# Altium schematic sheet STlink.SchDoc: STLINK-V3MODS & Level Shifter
size A4; Date: Not used; ApprovedBy: Not used; CheckedBy: Not used; Author: Not used; CompanyName: STMicroelectronics; DrawnBy: Not used; Engineer: Not used; Organization: Not used; Address1: Not used; Address2: Not used; Address3: Not used; Address4: Not used; DocumentNumber: Not used; Revision: Not used; SheetNumber: 6; SheetTotal: 6
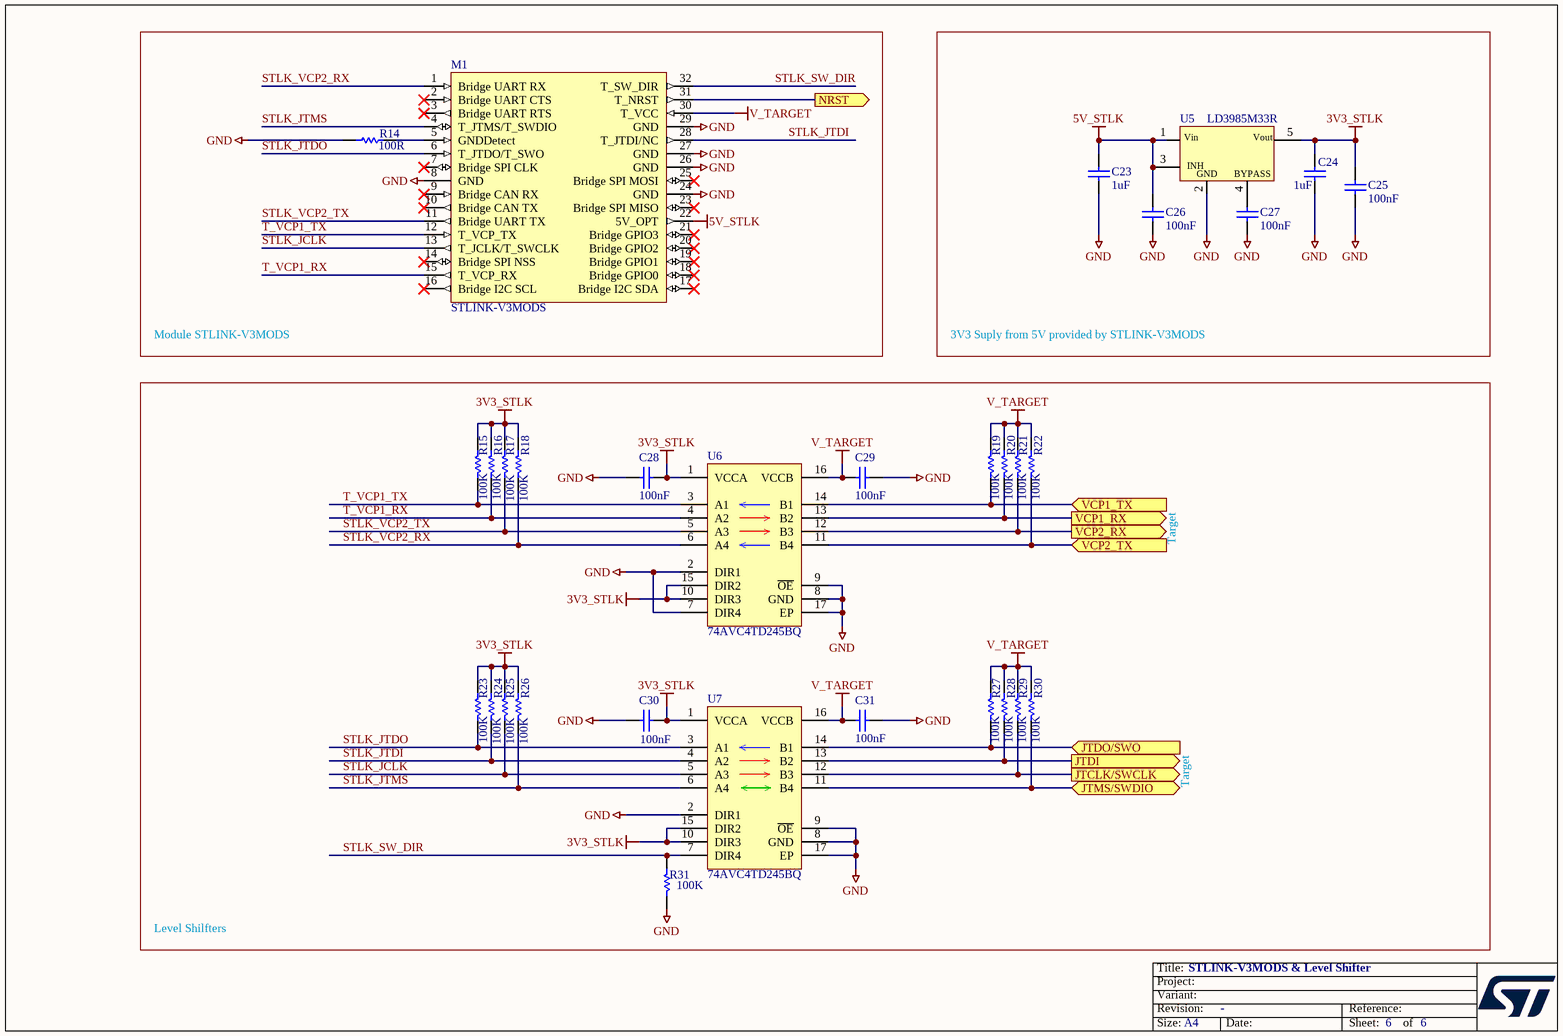
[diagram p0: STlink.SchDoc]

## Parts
C23  value 1uF  [C0402]  (hidden comment: Capacitor)
C24  value 1uF  [C0402]  (hidden comment: Capacitor)
C25  value 100nF  [C0402]  (hidden comment: Capacitor)
C26  value 100nF  [C0402]  (hidden comment: Capacitor)
C27  value 100nF  [C0402]  (hidden comment: Capacitor)
C28  value 100nF  [C0402]  (hidden comment: Capacitor)
C29  value 100nF  [C0402]  (hidden comment: Capacitor)
C30  value 100nF  [C0402]  (hidden comment: Capacitor)
C31  value 100nF  [C0402]  (hidden comment: Capacitor)
M1  STLINK-V3MODS  [MOD_STLINK-V3M_MB1467]
R14  value 100R  [R0402]  (hidden comment: Resistor)
R15  value 100K  [R0402]  (hidden comment: Resistor)
R16  value 100K  [R0402]  (hidden comment: Resistor)
R17  value 100K  [R0402]  (hidden comment: Resistor)
R18  value 100K  [R0402]  (hidden comment: Resistor)
R19  value 100K  [R0402]  (hidden comment: Resistor)
R20  value 100K  [R0402]  (hidden comment: Resistor)
R21  value 100K  [R0402]  (hidden comment: Resistor)
R22  value 100K  [R0402]  (hidden comment: Resistor)
R23  value 100K  [R0402]  (hidden comment: Resistor)
R24  value 100K  [R0402]  (hidden comment: Resistor)
R25  value 100K  [R0402]  (hidden comment: Resistor)
R26  value 100K  [R0402]  (hidden comment: Resistor)
R27  value 100K  [R0402]  (hidden comment: Resistor)
R28  value 100K  [R0402]  (hidden comment: Resistor)
R29  value 100K  [R0402]  (hidden comment: Resistor)
R30  value 100K  [R0402]  (hidden comment: Resistor)
R31  value 100K  [R0402]  (hidden comment: Resistor)
U5  LD3985M33R  [REG_SOT23-5L]
U6  74AVC4TD245BQ  [ICC_DHVQFN16-EPAD_SOT763-1_2P5X3P5_H0P85_P050]
U7  74AVC4TD245BQ  [ICC_DHVQFN16-EPAD_SOT763-1_2P5X3P5_H0P85_P050]

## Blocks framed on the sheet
Module STLINK-V3MODS: M1 R14
3V3 Suply from 5V provided by STLINK-V3MODS: C23-C27 U5

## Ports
JTCLK/SWCLK (out), JTDI (out), JTDO/SWO (in), JTMS/SWDIO (bidir), NRST (out), VCP1_RX (out), VCP1_TX (in), VCP2_RX (out), VCP2_TX (in)

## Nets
3V3_STLK: C24.2 C25.2 C28.1 C30.1 R15.2 R16.2 R17.2 R18.2 R23.2 R24.2 R25.2 R26.2 U5.5(Vout) U6.1(VCCA) U6.10(DIR3) U6.15(DIR2) U7.1(VCCA) U7.10(DIR3) U7.15(DIR2)
5V_STLK: C23.2 C26.2 M1.22(5V_OPT) U5.1(Vin) U5.3(CE)
GND: C23.1 C24.1 C25.1 C26.1 C27.1 C28.2 C29.1 C30.2 C31.1 M1.8(GND) M1.24(GND) M1.26(GND) M1.27(GND) M1.29(GND) R14.1 R31.2 U5.2(GND) U6.2(DIR1) U6.7(DIR4) U6.8(GND) U6.9(~{OE}) U6.17(EP) U7.2(DIR1) U7.8(GND) U7.9(~{OE}) U7.17(EP)
V_TARGET: C29.2 C31.2 M1.30(T_VCC) R19.2 R20.2 R21.2 R22.2 R27.2 R28.2 R29.2 R30.2 U6.16(VCCB) U7.16(VCCB)
JTCLK/SWCLK: R29.1 U7.12(B3) ; port JTCLK/SWCLK
JTDI: R28.1 U7.13(B2) ; port JTDI
JTDO/SWO: R27.1 U7.14(B1) ; port JTDO/SWO
JTMS/SWDIO: R30.1 U7.11(B4) ; port JTMS/SWDIO
NRST: M1.31(T_NRST) ; port NRST
STLK_JCLK: M1.13(T_JCLK/T_SWCLK) R25.1 U7.5(A3)
STLK_JTDI: M1.28(T_JTDI/NC) R24.1 U7.4(A2)
STLK_JTDO: M1.6(T_JTDO/T_SWO) R23.1 U7.3(A1)
STLK_JTMS: M1.4(T_JTMS/T_SWDIO) R26.1 U7.6(A4)
STLK_SW_DIR: M1.32(T_SW_DIR) R31.1 U7.7(DIR4)
STLK_VCP2_RX: M1.1(Bridge_UART_RX) R18.1 U6.6(A4)
STLK_VCP2_TX: M1.11(Bridge_UART_TX) R17.1 U6.5(A3)
T_VCP1_RX: M1.15(T_VCP_RX) R16.1 U6.4(A2)
T_VCP1_TX: M1.12(T_VCP_TX) R15.1 U6.3(A1)
VCP1_RX: R20.1 U6.13(B2) ; port VCP1_RX
VCP1_TX: R19.1 U6.14(B1) ; port VCP1_TX
VCP2_RX: R21.1 U6.12(B3) ; port VCP2_RX
VCP2_TX: R22.1 U6.11(B4) ; port VCP2_TX
NetC27_2: C27.2 U5.4(BYPASS)
NetM1_5: M1.5(GNDDetect) R14.2

Not connected (* = marked no-connect by the designer): M1 2(Bridge_UART_CTS)* 3(Bridge_UART_RTS)* 7(Bridge_SPI_CLK)* 9(Bridge_CAN_RX)* 10(Bridge_CAN_TX)* 14(Bridge_SPI_NSS)* 16(Bridge_I2C_SCL)* 17(Bridge_I2C_SDA)* 18(Bridge_GPIO0)* 19(Bridge_GPIO1)* 20(Bridge_GPIO2)* 21(Bridge_GPIO3)* 23(Bridge_SPI_MISO)* 25(Bridge_SPI_MOSI)*

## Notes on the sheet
- Target
- Level Shilfters

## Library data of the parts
C23 C24 = MCD-01722: Capacitor, MLCC, 1uF, 10V, X5R, +/-10%, 0402, T=0.5mm; Manufacturer_Part_Number: CC0402KRX5R6BB105; Manufacturer: YAGEO; Part_Preference: Recommended; Component_Country_Of_Origin: China
C25-C31 = MCD-02355: Capacitor, MLCC, 100nF, 25V, X7R, +/-10%, 0402, T=0.5mm; Part_Preference: Recommended; Manufacturer: WALSIN; Manufacturer_Part_Number: 0402B104K250CT; Order_Code_RS: 176-3114; Component_Country_Of_Origin: Unknown
M1 = MCD-01983: STLINK-V3MODS module; Part_Type: Misc; Part_Preference: Recommended; Manufacturer: STMICROELECTRONICS; Manufacturer_HQ_COO: EU; Order_Code_RS: 200-6065; Component_Country_Of_Origin: Unknown
R14 = MCD-00119: Resistor, 100R, 0402, +/-1%, 1/16W; Part_Preference: Not recommended; Manufacturer: YAGEO; Manufacturer_Part_Number: RC0402FR-07100RL; Component_Country_Of_Origin: China
R15-R31 = MCD-00059: Resistor, 100K, 0402, +/-1%, 1/16W; Manufacturer_Part_Number: RC0402FR-07100KL; Manufacturer: YAGEO; Part_Preference: Recommended; Component_Country_Of_Origin: China
U5 = MCD-00086: Ultra low drop-low noise BiCMOS voltage, regulators low ESR capacitors compatible; Part_Type: IC; Manufacturer: STMICROELECTRONICS; BMS_Part_Number: 9176161; Part_Preference: Recommended; Manufacturer_HQ_COO: EU; Component_Country_Of_Origin: China
U6 U7 = MCD-01945: 4-bit dual supply translating transceiver with configurable voltage translation; 3-state; Part_Type: IC; Manufacturer_Part_Number: 74AVC4TD245BQ,115; Manufacturer: NEXPERIA; Part_Preference: Recommended; Component_Country_Of_Origin: Thailand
